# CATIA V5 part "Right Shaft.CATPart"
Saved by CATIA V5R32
Part number: Right hand shaft
Bounding box of the stored display mesh (mm): x 0 to 100, y -35 to 35, z -35 to 35
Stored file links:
  D:\PROJECTS\Project 2022\CATIA V5 6R 2022\Resources\Part Files\c16_catia_v5_6r2022_prt\CV Joint-(Fig16-51)\Right Shaft.CATPart
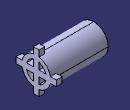
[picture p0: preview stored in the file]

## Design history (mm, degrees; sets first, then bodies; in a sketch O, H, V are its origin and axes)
Body1 (main body)
  Sketch1 on yz-plane, origin (0, 0, 0), H (0, 1, 0), V (0, 0, 1)
    circle A1 centre (0, 0) radius 25
    circle A2 centre (0, 0) radius 17.5
    radius A1 = 25
    radius A2 = 17.5
  Pad1: profile Sketch1, direction (1, 0, 0), length 100
  Sketch2 on end face of Pad1, origin (100, 0, 0), H (0, 1, 0), V (0, 0, 1)
    line L1 (5, 35) -> (5, -35)
    line L2 (5, -35) -> (-5, -35)
    line L3 (-5, -35) -> (-5, 35)
    line L4 (-5, 35) -> (5, 35)
    length L1 = 70
    length L4 = 10
    vertical: L1 V, L3 V
    horizontal: L2 H, L4 H
    equidistance: L1 L3 O, L2 L4 O
  Pad2: profile Sketch2, direction (-1, 0, 0), length 10
  CircPattern1: of the body so far, instances 2, angular step 90, axis from face of Pad1 from Sketch1.A1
